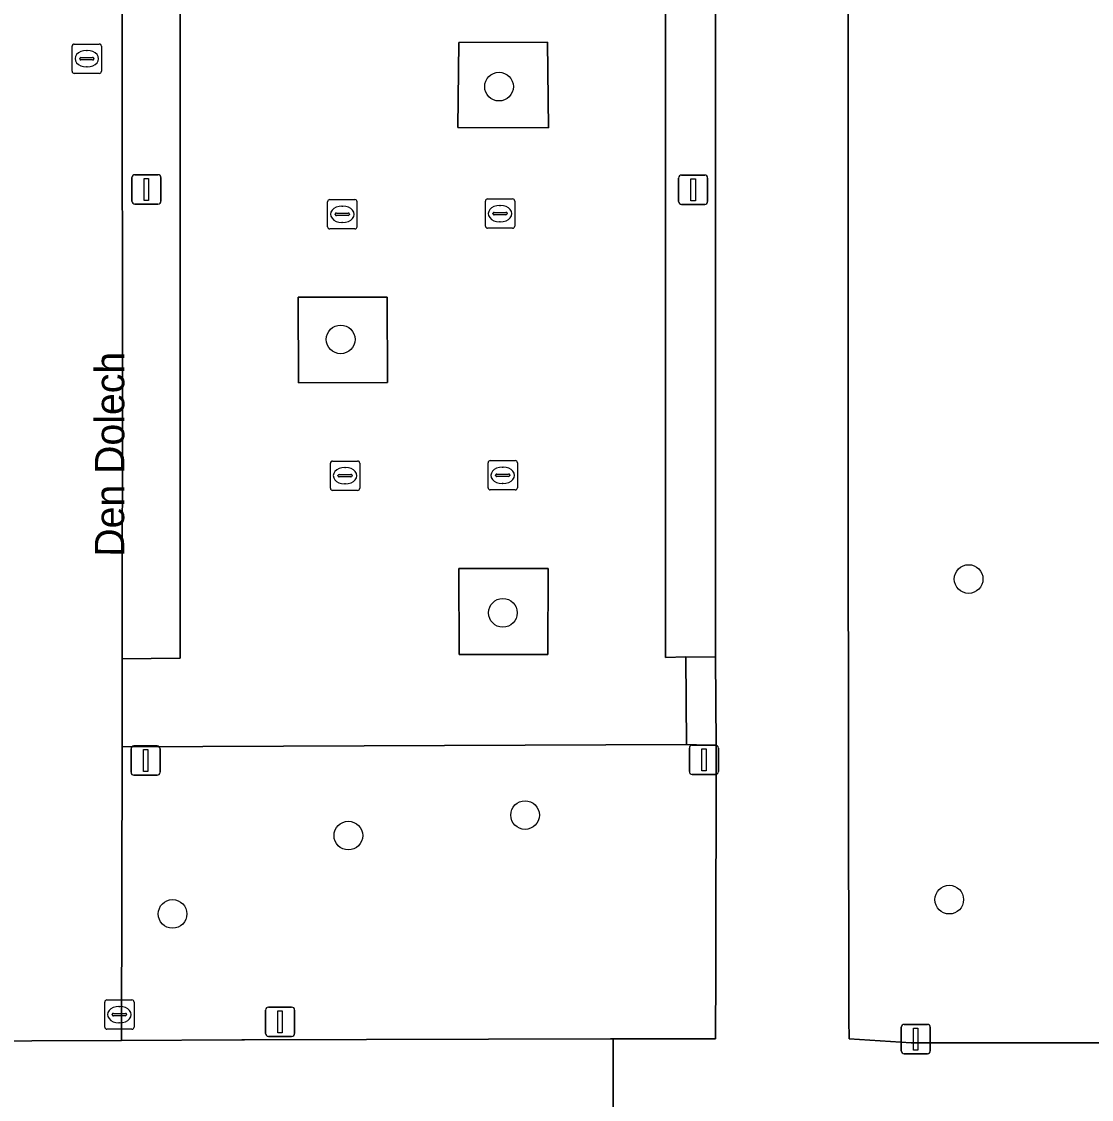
# Model space of a CAD drawing. Extents: x 161477 to 163040, y 383680 to 384871.
# Drawn here: x 161810.58 to 161847.07, y 384254.72 to 384291.47 of the extents above; entities that cross this region are included whole.
import ezdxf

# ---------------------------------------------------------------- set-up
doc = ezdxf.new("R2010")
doc.units = 0
for name, color, linetype in [('IMGEO_Boom', 7, 'Continuous'), ('IMGEO_Groenvoorziening', 7, 'Continuous'), ('IMGEO_Kolk', 7, 'Continuous'), ('IMGEO_Lichtmast', 7, 'Continuous'), ('IMGEO_Openbare_ruimte_label', 7, 'Continuous'), ('IMGEO_Parkeervlak_open', 7, 'Continuous'), ('IMGEO_Rijbaan_lokaal_gesloten', 7, 'Continuous'), ('IMGEO_Rijbaan_lokaal_open', 7, 'Continuous'), ('IMGEO_Rioolput', 7, 'Continuous'), ('IMGEO_Voetpad_op_trap', 7, 'Continuous'), ('IMGEO_Voetpad_open', 7, 'Continuous')]:
    doc.layers.add(name, color=color, linetype=linetype)

msp = doc.modelspace()

# ---------------------------------------------------------------- linework, layer by layer
at = {"layer": 'IMGEO_Boom'}
for centre in [(161826.863, 384289.254), (161821.463, 384280.633), (161842.878, 384272.462), (161826.995, 384271.31), (161827.751, 384264.412), (161821.725, 384263.714), (161842.217, 384261.529), (161815.73, 384261.042)]:
    msp.add_circle(centre, 0.489, dxfattribs=at)
at = {"layer": 'IMGEO_Groenvoorziening'}
for points in [[(161848.995, 384288.764), (161848.999, 384306.584), (161848.999, 384306.752), (161848.275, 384306.754), (161840.752, 384306.775), (161838.752, 384306.78), (161838.765, 384291.613), (161838.768, 384275.095), (161838.797, 384257.441), (161838.799, 384256.777), (161840.921, 384256.647), (161859.948, 384256.647), (161861.058, 384256.647), (161864.088, 384256.647), (161864.127, 384261.629), (161864.233, 384261.629), (161864.212, 384267.051), (161855.033, 384267.033), (161855.033, 384267.359), (161854.547, 384267.358), (161849.004, 384267.346)], [(161815.992, 384301.962), (161814.049, 384301.923), (161814.031, 384299.293), (161814.015, 384290.015), (161814.02, 384280.045), (161814.017, 384269.739), (161815.984, 384269.764)], [(161834.237, 384301.912), (161833.222, 384301.901), (161832.538, 384301.901), (161832.535, 384269.792), (161833.234, 384269.806), (161834.244, 384269.796), (161834.25, 384284.041)], [(161828.521, 384290.769), (161825.488, 384290.762), (161825.461, 384287.864), (161828.546, 384287.847)], [(161823.054, 384282.072), (161820.017, 384282.072), (161820.02, 384279.152), (161823.061, 384279.164)], [(161828.538, 384272.827), (161825.493, 384272.821), (161825.503, 384269.888), (161825.883, 384269.888), (161828.533, 384269.888)], [(161834.263, 384266.79), (161833.26, 384266.815), (161814.017, 384266.743), (161813.986, 384256.731), (161818.097, 384256.747), (161818.189, 384256.747), (161830.666, 384256.777), (161830.757, 384256.777), (161834.249, 384256.778), (161834.252, 384259.072)]]:
    msp.add_lwpolyline(points, close=True, dxfattribs=at)
at = {"layer": 'IMGEO_Kolk'}
for p, q in [((161821.019, 384284.475), (161821.019, 384285.327)), ((161821.094, 384285.401), (161821.946, 384285.401)), ((161822.02, 384285.327), (161822.02, 384284.475)), ((161826.397, 384284.498), (161826.397, 384285.35)), ((161826.472, 384285.424), (161827.324, 384285.424)), ((161827.398, 384285.35), (161827.398, 384284.498)), ((161821.278, 384284.895), (161821.278, 384284.907)), ((161821.716, 384284.858), (161821.318, 384284.858)), ((161821.321, 384284.944), (161821.719, 384284.944)), ((161821.507, 384285.181), (161821.532, 384285.181)), ((161821.762, 384284.907), (161821.762, 384284.895)), ((161826.656, 384284.918), (161826.656, 384284.93)), ((161827.094, 384284.881), (161826.696, 384284.881)), ((161826.699, 384284.967), (161827.097, 384284.967)), ((161826.885, 384285.204), (161826.91, 384285.204)), ((161827.14, 384284.93), (161827.14, 384284.918)), ((161821.53, 384284.621), (161821.505, 384284.621)), ((161826.908, 384284.644), (161826.883, 384284.644)), ((161821.946, 384284.401), (161821.094, 384284.401)), ((161827.324, 384284.424), (161826.472, 384284.424)), ((161821.112, 384275.561), (161821.112, 384276.413)), ((161821.187, 384276.487), (161822.039, 384276.487)), ((161822.113, 384276.413), (161822.113, 384275.561)), ((161826.488, 384275.574), (161826.488, 384276.426)), ((161826.563, 384276.5), (161827.415, 384276.5)), ((161827.489, 384276.426), (161827.489, 384275.574)), ((161821.414, 384276.03), (161821.812, 384276.03)), ((161821.6, 384276.267), (161821.625, 384276.267)), ((161826.79, 384276.043), (161827.188, 384276.043)), ((161826.976, 384276.28), (161827.001, 384276.28)), ((161821.371, 384275.981), (161821.371, 384275.993)), ((161821.809, 384275.944), (161821.411, 384275.944)), ((161821.623, 384275.707), (161821.598, 384275.707)), ((161821.855, 384275.993), (161821.855, 384275.981)), ((161826.747, 384275.994), (161826.747, 384276.006)), ((161827.185, 384275.957), (161826.787, 384275.957)), ((161826.999, 384275.72), (161826.974, 384275.72)), ((161827.231, 384276.006), (161827.231, 384275.994)), ((161822.039, 384275.487), (161821.187, 384275.487)), ((161827.415, 384275.5), (161826.563, 384275.5)), ((161813.415, 384257.183), (161813.415, 384258.035)), ((161813.49, 384258.109), (161814.342, 384258.109)), ((161814.416, 384258.035), (161814.416, 384257.183)), ((161813.717, 384257.652), (161814.115, 384257.652)), ((161813.903, 384257.889), (161813.928, 384257.889)), ((161813.674, 384257.603), (161813.674, 384257.615)), ((161814.112, 384257.566), (161813.714, 384257.566)), ((161813.926, 384257.329), (161813.901, 384257.329)), ((161814.158, 384257.615), (161814.158, 384257.603)), ((161814.342, 384257.109), (161813.49, 384257.109))]:
    msp.add_line(p, q, dxfattribs=at)
for points in [[(161821.019, 384284.475), (161821.019, 384285.327)], [(161821.094, 384285.401), (161821.946, 384285.401)], [(161822.02, 384285.327), (161822.02, 384284.475)], [(161826.397, 384284.498), (161826.397, 384285.35)], [(161826.472, 384285.424), (161827.324, 384285.424)], [(161827.398, 384285.35), (161827.398, 384284.498)], [(161821.946, 384284.401), (161821.094, 384284.401)], [(161827.324, 384284.424), (161826.472, 384284.424)], [(161821.112, 384275.561), (161821.112, 384276.413)], [(161821.187, 384276.487), (161822.039, 384276.487)], [(161822.113, 384276.413), (161822.113, 384275.561)], [(161826.488, 384275.574), (161826.488, 384276.426)], [(161826.563, 384276.5), (161827.415, 384276.5)], [(161827.489, 384276.426), (161827.489, 384275.574)], [(161822.039, 384275.487), (161821.187, 384275.487)], [(161827.415, 384275.5), (161826.563, 384275.5)], [(161813.415, 384257.183), (161813.415, 384258.035)], [(161813.49, 384258.109), (161814.342, 384258.109)], [(161814.416, 384258.035), (161814.416, 384257.183)], [(161814.342, 384257.109), (161813.49, 384257.109)]]:
    msp.add_lwpolyline(points, dxfattribs=at)
for centre, radius, start, end in [((161821.096, 384285.325), 0.0765, 91.552, 178.448), ((161821.096, 384285.325), 0.0765, 91.552, 178.448), ((161821.944, 384285.325), 0.0765, 1.552, 88.448), ((161821.944, 384285.325), 0.0765, 1.552, 88.448), ((161826.474, 384285.348), 0.0765, 91.552, 178.448), ((161826.474, 384285.348), 0.0765, 91.552, 178.448), ((161827.322, 384285.348), 0.0765, 1.552, 88.448), ((161827.322, 384285.348), 0.0765, 1.552, 88.448), ((161821.318, 384284.904), 0.0403, 85.8775, 175.7526), ((161821.315, 384284.894), 0.0366, 178.938, 274.7102), ((161821.719, 384284.901), 0.043, 264.8664, 352.4533), ((161821.723, 384284.906), 0.0386, 1.7309, 96.639), ((161826.696, 384284.927), 0.0403, 85.8775, 175.7526), ((161826.693, 384284.917), 0.0366, 178.938, 274.7102), ((161827.097, 384284.924), 0.043, 264.8664, 352.4533), ((161827.101, 384284.929), 0.0386, 1.7309, 96.639), ((161826.474, 384284.5), 0.0765, 181.552, 268.448), ((161826.474, 384284.5), 0.0765, 181.552, 268.448), ((161827.322, 384284.5), 0.0765, 271.552, 358.448), ((161827.322, 384284.5), 0.0765, 271.552, 358.448), ((161821.096, 384284.477), 0.0765, 181.552, 268.448), ((161821.096, 384284.477), 0.0765, 181.552, 268.448), ((161821.944, 384284.477), 0.0765, 271.552, 358.448), ((161821.944, 384284.477), 0.0765, 271.552, 358.448), ((161821.189, 384276.411), 0.0765, 91.552, 178.448), ((161821.189, 384276.411), 0.0765, 91.552, 178.448), ((161822.037, 384276.411), 0.0765, 1.552, 88.448), ((161822.037, 384276.411), 0.0765, 1.552, 88.448), ((161826.565, 384276.424), 0.0765, 91.552, 178.448), ((161826.565, 384276.424), 0.0765, 91.552, 178.448), ((161827.413, 384276.424), 0.0765, 1.552, 88.448), ((161827.413, 384276.424), 0.0765, 1.552, 88.448), ((161821.411, 384275.99), 0.0403, 85.8775, 175.7526), ((161821.816, 384275.992), 0.0386, 1.7309, 96.639), ((161826.787, 384276.003), 0.0403, 85.8775, 175.7526), ((161827.192, 384276.005), 0.0386, 1.7309, 96.639), ((161821.408, 384275.98), 0.0366, 178.938, 274.7102), ((161821.812, 384275.987), 0.043, 264.8664, 352.4533), ((161826.784, 384275.993), 0.0366, 178.938, 274.7102), ((161827.188, 384276), 0.043, 264.8664, 352.4533), ((161821.189, 384275.563), 0.0765, 181.552, 268.448), ((161821.189, 384275.563), 0.0765, 181.552, 268.448), ((161822.037, 384275.563), 0.0765, 271.552, 358.448), ((161822.037, 384275.563), 0.0765, 271.552, 358.448), ((161826.565, 384275.576), 0.0765, 181.552, 268.448), ((161826.565, 384275.576), 0.0765, 181.552, 268.448), ((161827.413, 384275.576), 0.0765, 271.552, 358.448), ((161827.413, 384275.576), 0.0765, 271.552, 358.448), ((161813.492, 384258.033), 0.0765, 91.552, 178.448), ((161813.492, 384258.033), 0.0765, 91.552, 178.448), ((161814.34, 384258.033), 0.0765, 1.552, 88.448), ((161814.34, 384258.033), 0.0765, 1.552, 88.448), ((161813.714, 384257.612), 0.0403, 85.8775, 175.7526), ((161814.119, 384257.614), 0.0386, 1.7309, 96.639), ((161813.711, 384257.602), 0.0366, 178.938, 274.7102), ((161814.115, 384257.609), 0.043, 264.8664, 352.4533), ((161813.492, 384257.185), 0.0765, 181.552, 268.448), ((161813.492, 384257.185), 0.0765, 181.552, 268.448), ((161814.34, 384257.185), 0.0765, 271.552, 358.448), ((161814.34, 384257.185), 0.0765, 271.552, 358.448)]:
    msp.add_arc(centre, radius, start, end, dxfattribs=at)
for centre, major_axis, ratio, start_param, end_param in [((161821.506, 384284.901), (-0.387, 0.002), 0.722429, 4.712389, 7.853982), ((161821.531, 384284.901), (-0.39, 0.002), 0.717154, 1.570796, 4.712389), ((161826.884, 384284.924), (-0.387, 0.002), 0.722429, 4.712389, 7.853982), ((161826.909, 384284.924), (-0.39, 0.002), 0.717154, 1.570796, 4.712389), ((161821.599, 384275.987), (-0.387, 0.002), 0.722429, 4.712389, 7.853982), ((161821.624, 384275.987), (-0.39, 0.002), 0.717154, 1.570796, 4.712389), ((161826.975, 384276), (-0.387, 0.002), 0.722429, 4.712389, 7.853982), ((161827, 384276), (-0.39, 0.002), 0.717154, 1.570796, 4.712389), ((161813.902, 384257.609), (-0.387, 0.002), 0.722429, 4.712389, 7.853982), ((161813.927, 384257.609), (-0.39, 0.002), 0.717154, 1.570796, 4.712389)]:
    msp.add_ellipse(centre, major_axis=major_axis, ratio=ratio, start_param=start_param, end_param=end_param, dxfattribs=at)
at = {"layer": 'IMGEO_Lichtmast'}
for p, q in [((161814.343, 384285.35), (161814.343, 384286.15)), ((161814.343, 384286.15), (161814.343, 384285.35)), ((161814.443, 384286.25), (161815.233, 384286.25)), ((161815.233, 384286.25), (161814.443, 384286.25)), ((161815.333, 384286.15), (161815.333, 384285.35)), ((161815.333, 384285.35), (161815.333, 384286.15)), ((161832.988, 384285.338), (161832.988, 384286.138)), ((161832.988, 384286.138), (161832.988, 384285.338)), ((161833.088, 384286.238), (161833.878, 384286.238)), ((161833.878, 384286.238), (161833.088, 384286.238)), ((161833.978, 384286.138), (161833.978, 384285.338)), ((161833.978, 384285.338), (161833.978, 384286.138)), ((161815.233, 384285.25), (161814.443, 384285.25)), ((161814.443, 384285.25), (161815.233, 384285.25)), ((161833.878, 384285.238), (161833.088, 384285.238)), ((161833.088, 384285.238), (161833.878, 384285.238)), ((161814.314, 384265.872), (161814.314, 384266.672)), ((161814.314, 384266.672), (161814.314, 384265.872)), ((161814.414, 384266.772), (161815.204, 384266.772)), ((161815.204, 384266.772), (161814.414, 384266.772)), ((161815.304, 384266.672), (161815.304, 384265.872)), ((161815.304, 384265.872), (161815.304, 384266.672)), ((161833.354, 384265.897), (161833.354, 384266.697)), ((161833.354, 384266.697), (161833.354, 384265.897)), ((161833.454, 384266.797), (161834.244, 384266.797)), ((161834.244, 384266.797), (161833.454, 384266.797)), ((161834.344, 384266.697), (161834.344, 384265.897)), ((161834.344, 384265.897), (161834.344, 384266.697)), ((161815.204, 384265.772), (161814.414, 384265.772)), ((161814.414, 384265.772), (161815.204, 384265.772)), ((161834.244, 384265.797), (161833.454, 384265.797)), ((161833.454, 384265.797), (161834.244, 384265.797)), ((161818.901, 384256.964), (161818.901, 384257.764)), ((161818.901, 384257.764), (161818.901, 384256.964)), ((161819.001, 384257.864), (161819.791, 384257.864)), ((161819.791, 384257.864), (161819.001, 384257.864)), ((161819.891, 384257.764), (161819.891, 384256.964)), ((161819.891, 384256.964), (161819.891, 384257.764)), ((161840.581, 384256.375), (161840.581, 384257.175)), ((161840.581, 384257.175), (161840.581, 384256.375)), ((161840.681, 384257.275), (161841.471, 384257.275)), ((161841.471, 384257.275), (161840.681, 384257.275)), ((161841.571, 384257.175), (161841.571, 384256.375)), ((161841.571, 384256.375), (161841.571, 384257.175)), ((161819.791, 384256.864), (161819.001, 384256.864)), ((161819.001, 384256.864), (161819.791, 384256.864)), ((161841.471, 384256.275), (161840.681, 384256.275)), ((161840.681, 384256.275), (161841.471, 384256.275))]:
    msp.add_line(p, q, dxfattribs=at)
for points in [[(161814.763, 384286.125), (161814.913, 384286.125), (161814.913, 384285.375), (161814.763, 384285.375), (161814.763, 384286.125)], [(161833.408, 384286.113), (161833.558, 384286.113), (161833.558, 384285.363), (161833.408, 384285.363), (161833.408, 384286.113)], [(161814.734, 384266.647), (161814.884, 384266.647), (161814.884, 384265.897), (161814.734, 384265.897), (161814.734, 384266.647)], [(161833.774, 384266.672), (161833.924, 384266.672), (161833.924, 384265.922), (161833.774, 384265.922), (161833.774, 384266.672)], [(161819.321, 384257.739), (161819.471, 384257.739), (161819.471, 384256.989), (161819.321, 384256.989), (161819.321, 384257.739)], [(161841.001, 384257.15), (161841.151, 384257.15), (161841.151, 384256.4), (161841.001, 384256.4), (161841.001, 384257.15)]]:
    msp.add_lwpolyline(points, dxfattribs=at)
for centre, start, end in [((161814.443, 384286.15), 90, 180), ((161814.443, 384286.15), 90, 180), ((161815.233, 384286.15), 0, 90), ((161815.233, 384286.15), 360, 90), ((161833.088, 384286.138), 90, 180), ((161833.088, 384286.138), 90, 180), ((161833.878, 384286.138), 0, 90), ((161833.878, 384286.138), 360, 90), ((161814.443, 384285.35), 180, 270), ((161814.443, 384285.35), 180, 270), ((161815.233, 384285.35), 270, 0), ((161815.233, 384285.35), 270, 0), ((161833.088, 384285.338), 180, 270), ((161833.088, 384285.338), 180, 270), ((161833.878, 384285.338), 270, 0), ((161833.878, 384285.338), 270, 0), ((161814.414, 384266.672), 90, 180), ((161814.414, 384266.672), 90, 180), ((161815.204, 384266.672), 0, 90), ((161815.204, 384266.672), 360, 90), ((161833.454, 384266.697), 90, 180), ((161833.454, 384266.697), 90, 180), ((161834.244, 384266.697), 0, 90), ((161834.244, 384266.697), 360, 90), ((161814.414, 384265.872), 180, 270), ((161814.414, 384265.872), 180, 270), ((161815.204, 384265.872), 270, 0), ((161815.204, 384265.872), 270, 0), ((161833.454, 384265.897), 180, 270), ((161833.454, 384265.897), 180, 270), ((161834.244, 384265.897), 270, 0), ((161834.244, 384265.897), 270, 0), ((161819.001, 384257.764), 90, 180), ((161819.001, 384257.764), 90, 180), ((161819.791, 384257.764), 0, 90), ((161819.791, 384257.764), 360, 90), ((161819.001, 384256.964), 180, 270), ((161819.001, 384256.964), 180, 270), ((161819.791, 384256.964), 270, 0), ((161819.791, 384256.964), 270, 0), ((161840.681, 384257.175), 90, 180), ((161840.681, 384257.175), 90, 180), ((161841.471, 384257.175), 0, 90), ((161841.471, 384257.175), 360, 90), ((161840.681, 384256.375), 180, 270), ((161840.681, 384256.375), 180, 270), ((161841.471, 384256.375), 270, 0), ((161841.471, 384256.375), 270, 0)]:
    msp.add_arc(centre, 0.1, start, end, dxfattribs=at)
at = {"layer": 'IMGEO_Parkeervlak_open'}
for points in [[(161832.538, 384301.901), (161833.222, 384301.901), (161833.227, 384304.914), (161814.057, 384304.937), (161814.049, 384301.923), (161815.992, 384301.962), (161815.984, 384269.764), (161814.017, 384269.739), (161814.017, 384266.743), (161833.26, 384266.815), (161833.234, 384269.806), (161832.535, 384269.792)], [(161825.461, 384287.864), (161825.488, 384290.762), (161828.521, 384290.769), (161828.546, 384287.847)], [(161823.061, 384279.164), (161820.02, 384279.152), (161820.017, 384282.072), (161823.054, 384282.072)], [(161828.538, 384272.827), (161828.533, 384269.888), (161825.883, 384269.888), (161825.503, 384269.888), (161825.493, 384272.821)]]:
    msp.add_lwpolyline(points, close=True, dxfattribs=at)
at = {"layer": 'IMGEO_Rijbaan_lokaal_gesloten'}
msp.add_lwpolyline([(161831.783, 384190.88), (161831.783, 384192.925), (161831.783, 384203.307), (161823.675, 384203.32), (161823.587, 384236.681), (161830.757, 384236.661), (161830.757, 384256.777), (161830.666, 384256.777), (161818.189, 384256.747), (161818.097, 384256.747), (161813.986, 384256.731), (161807.863, 384256.708), (161805.467, 384256.687), (161804.935, 384256.696), (161802.787, 384257.256), (161799.843, 384258.917), (161796.611, 384261.596), (161784.23, 384275.764)], dxfattribs=at)
at = {"layer": 'IMGEO_Rijbaan_lokaal_open'}
msp.add_lwpolyline([(161807.863, 384256.708), (161813.986, 384256.731), (161814.017, 384266.743), (161814.017, 384269.739), (161814.02, 384280.045), (161814.015, 384290.015), (161814.031, 384299.293), (161814.049, 384301.923), (161814.057, 384304.937), (161814.034, 384306.822), (161814.043, 384312.528), (161814.051, 384317.437), (161814.06, 384323.352), (161814.035, 384329.719)], dxfattribs=at)
at = {"layer": 'IMGEO_Rioolput'}
for p, q in [((161812.305, 384289.781), (161812.305, 384290.633)), ((161812.38, 384290.707), (161813.232, 384290.707)), ((161812.793, 384290.487), (161812.818, 384290.487)), ((161813.306, 384290.633), (161813.306, 384289.781)), ((161812.564, 384290.201), (161812.564, 384290.213)), ((161813.002, 384290.164), (161812.604, 384290.164)), ((161812.607, 384290.25), (161813.005, 384290.25)), ((161813.048, 384290.213), (161813.048, 384290.201)), ((161813.232, 384289.707), (161812.38, 384289.707)), ((161812.816, 384289.927), (161812.791, 384289.927))]:
    msp.add_line(p, q, dxfattribs=at)
for points in [[(161812.305, 384289.781), (161812.305, 384290.633)], [(161812.38, 384290.707), (161813.232, 384290.707)], [(161813.306, 384290.633), (161813.306, 384289.781)], [(161813.232, 384289.707), (161812.38, 384289.707)]]:
    msp.add_lwpolyline(points, dxfattribs=at)
for centre, radius, start, end in [((161812.382, 384290.631), 0.0765, 91.552, 178.448), ((161812.382, 384290.631), 0.0765, 91.552, 178.448), ((161813.23, 384290.631), 0.0765, 1.552, 88.448), ((161813.23, 384290.631), 0.0765, 1.552, 88.448), ((161812.604, 384290.21), 0.0403, 85.8775, 175.7526), ((161812.601, 384290.2), 0.0366, 178.938, 274.7102), ((161813.005, 384290.207), 0.043, 264.8664, 352.4533), ((161813.009, 384290.212), 0.0386, 1.7309, 96.639), ((161812.382, 384289.783), 0.0765, 181.552, 268.448), ((161812.382, 384289.783), 0.0765, 181.552, 268.448), ((161813.23, 384289.783), 0.0765, 271.552, 358.448), ((161813.23, 384289.783), 0.0765, 271.552, 358.448)]:
    msp.add_arc(centre, radius, start, end, dxfattribs=at)
for centre, major_axis, ratio, start_param, end_param in [((161812.792, 384290.207), (-0.387, 0.002), 0.722429, 4.712389, 7.853982), ((161812.817, 384290.207), (-0.39, 0.002), 0.717154, 1.570796, 4.712389)]:
    msp.add_ellipse(centre, major_axis=major_axis, ratio=ratio, start_param=start_param, end_param=end_param, dxfattribs=at)
at = {"layer": 'IMGEO_Voetpad_op_trap'}
msp.add_lwpolyline([(161834.244, 384269.796), (161833.234, 384269.806), (161833.26, 384266.815), (161834.263, 384266.79)], close=True, dxfattribs=at)
at = {"layer": 'IMGEO_Voetpad_open'}
for points in [[(161814.035, 384329.719), (161814.06, 384323.352), (161814.051, 384317.437), (161814.043, 384312.528), (161814.034, 384306.822), (161834.233, 384306.821), (161834.252, 384304.905), (161834.237, 384301.912), (161834.25, 384284.041), (161834.244, 384269.796), (161834.263, 384266.79), (161834.252, 384259.072), (161834.249, 384256.778), (161830.757, 384256.777), (161830.757, 384236.661)], [(161859.948, 384256.647), (161840.921, 384256.647), (161838.799, 384256.777), (161838.797, 384257.441), (161838.768, 384275.095), (161838.765, 384291.613), (161838.752, 384306.78), (161840.752, 384306.775), (161848.275, 384306.754)]]:
    msp.add_lwpolyline(points, dxfattribs=at)

# ---------------------------------------------------------------- texts
at = {"layer": 'IMGEO_Openbare_ruimte_label'}
msp.add_text('Den Dolech', height=1, rotation=89.9427, dxfattribs=at).set_placement((161814.08, 384273.223))

doc.saveas('drawing.dxf')
